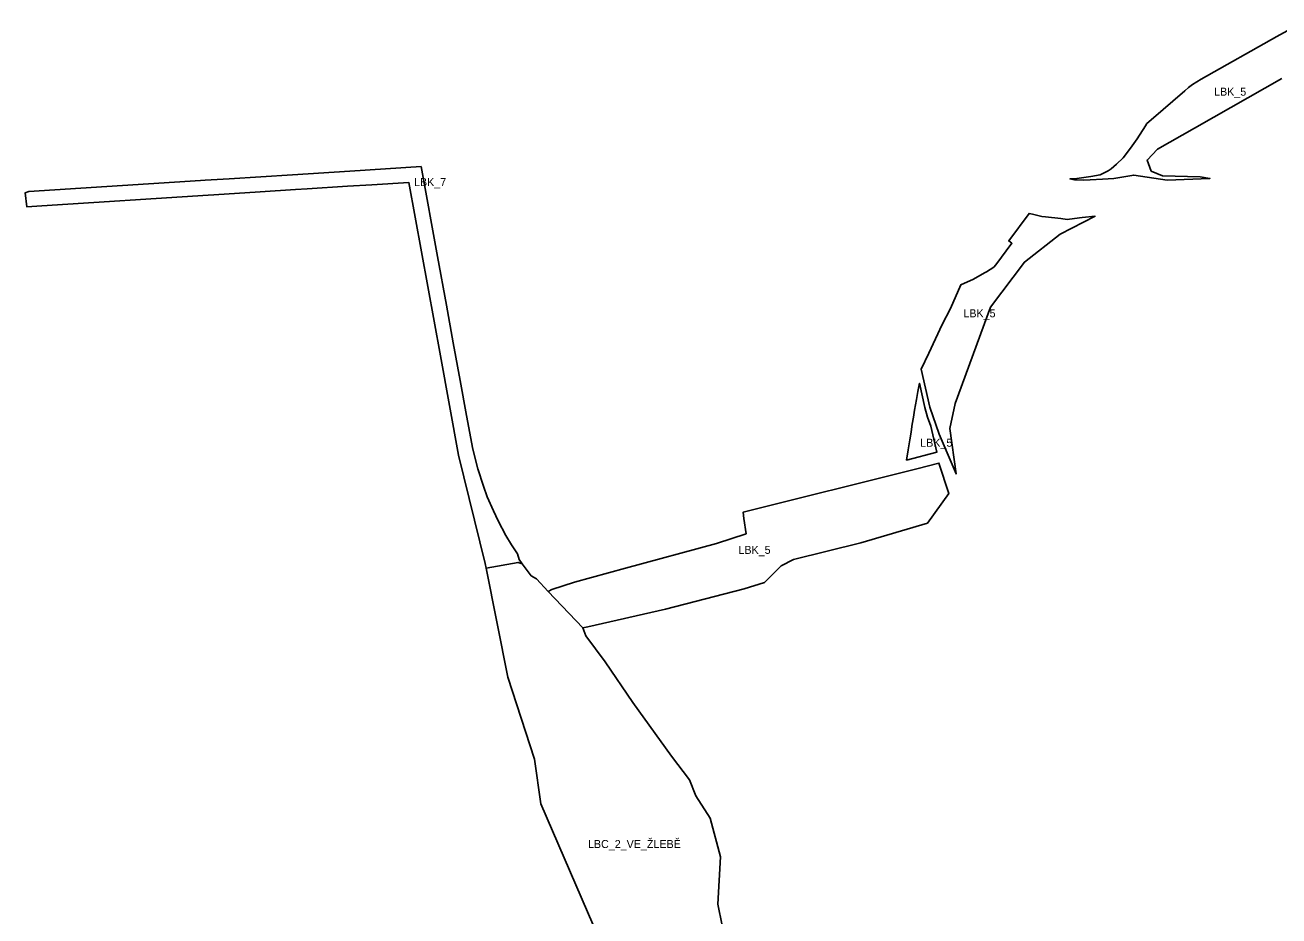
# Model space of a CAD drawing. Extents: x -521939 to -516426, y -1197857 to -1189576.
# Drawn here: x -519963 to -518710, y -1193727 to -1192836 of the extents above; entities that cross this region are included whole.
import ezdxf

# ---------------------------------------------------------------- set-up
doc = ezdxf.new("R2010")
doc.units = 0
doc.layers.add('91270013', color=7, linetype='Continuous')
doc.layers.add('91280013', color=7, linetype='Continuous')

msp = doc.modelspace()

# ---------------------------------------------------------------- linework, layer by layer
at = {"layer": '91270013'}
for points in [[(-519389.47, -1193750.04), (-519447.84, -1193614.85), (-519453.95, -1193570.4), (-519480.86, -1193488.16), (-519502.33, -1193379.15), (-519470.46, -1193373.47), (-519466.38, -1193375.11), (-519457.37, -1193386.9), (-519452.18, -1193390.07), (-519440.32, -1193402.59), (-519405.79, -1193439.04)], [(-519405.79, -1193439.04), (-519402.88, -1193446.79), (-519383.3, -1193472.91), (-519355.68, -1193513.49), (-519316.99, -1193567.29), (-519298.97, -1193590.8), (-519292.71, -1193607.08), (-519278.45, -1193629.39), (-519268.16, -1193667.94), (-519270.68, -1193715.28), (-519266.62, -1193736.71)]]:
    msp.add_lwpolyline(points, dxfattribs=at)
at = {"layer": '91280013'}
for points in [[(-518858.28, -1192959.18), (-518851.6, -1192949.85), (-518843.32, -1192936.91), (-518841.93, -1192934.75), (-518837.69, -1192931.06), (-518804.08, -1192901.83), (-518800.23, -1192898.65), (-518796.23, -1192895.68), (-518792.08, -1192892.91), (-518787.8, -1192890.35), (-518712.04, -1192847.75), (-518691.51, -1192836.21)], [(-518707.15, -1192889.79), (-518774.96, -1192928.3), (-518794.45, -1192939.2), (-518831.52, -1192960.42), (-518841.74, -1192971.22), (-518837.66, -1192982.24), (-518826.37, -1192986.96), (-518788.86, -1192987.81), (-518779.05, -1192989.61), (-518821.67, -1192991.23), (-518855.17, -1192986.26), (-518866.91, -1192988.22), (-518875.1, -1192989.54), (-518886.48, -1192990.45), (-518898.64, -1192990.98), (-518905.82, -1192991.22), (-518911.52, -1192991.08), (-518914.36, -1192990.89), (-518918.87, -1192990), (-518912.11, -1192989.78), (-518897.98, -1192987.5), (-518888.53, -1192985.94), (-518880.78, -1192981.82), (-518877.56, -1192980.06), (-518872.22, -1192975.24), (-518865.75, -1192969.09), (-518858.28, -1192959.18)], [(-519502.33, -1193379.15), (-519503.38, -1193374.77), (-519529.92, -1193266.42), (-519548.08, -1193166.93), (-519579.74, -1192993.48), (-519616.64, -1192995.84), (-519640.92, -1192997.38), (-519681.4, -1192999.94), (-519693.03, -1193000.71), (-519728.13, -1193002.94), (-519774.46, -1193005.9), (-519780.28, -1193006.26), (-519946.52, -1193016.85), (-519961.59, -1193017.82), (-519963.23, -1193004.02), (-519959.5, -1193002.65), (-519787.9, -1192991.72), (-519783.15, -1192991.42), (-519777.13, -1192991.04), (-519759.2, -1192989.89), (-519727.53, -1192987.89), (-519695.85, -1192985.85), (-519638.79, -1192982.16), (-519567.38, -1192977.66), (-519550.99, -1193067.69), (-519542.14, -1193116.18), (-519535.25, -1193153.85), (-519528.39, -1193191.55), (-519522, -1193226.57), (-519515.74, -1193260.34), (-519510.86, -1193279.84), (-519505.08, -1193297.39), (-519501.24, -1193308), (-519495.18, -1193322.01), (-519490.34, -1193332.09), (-519482.58, -1193346.45), (-519476.92, -1193356.09), (-519471.11, -1193364.85), (-519469.48, -1193370.72), (-519466.38, -1193375.11), (-519470.46, -1193373.47), (-519502.33, -1193379.15)], [(-519015.15, -1193090.46), (-519004.43, -1193084.1), (-519002.31, -1193082.85), (-518994.93, -1193078.21), (-518993.12, -1193076.06), (-518976.91, -1193054.31), (-518980, -1193052), (-518959.64, -1193024.58), (-518956.41, -1193025.34), (-518946.89, -1193027.59), (-518943.36, -1193028), (-518927.91, -1193029.78), (-518921.63, -1193030.5), (-518914.19, -1193029.54), (-518906.5, -1193028.54), (-518893.72, -1193027.32), (-518928.64, -1193045.14), (-518964.46, -1193073.28), (-518998.24, -1193118.29), (-519033.58, -1193214.67), (-519039.05, -1193239.66), (-519032.72, -1193285.1), (-519049.46, -1193245.15), (-519058.78, -1193218.39), (-519067.63, -1193180.4), (-519060.07, -1193164.39), (-519046.53, -1193135.65), (-519038.42, -1193119.66), (-519027.86, -1193095.83), (-519015.15, -1193090.46)], [(-519072.39, -1193210.54), (-519070.86, -1193202.48), (-519069.34, -1193194.44), (-519063.8, -1193218.73), (-519061.2, -1193228.34), (-519057.96, -1193237.27), (-519051.78, -1193263.19), (-519082.09, -1193271.2), (-519080.49, -1193261.05), (-519078.89, -1193250.9), (-519078.88, -1193250.89), (-519078.88, -1193250.88), (-519077.66, -1193243.14), (-519077.23, -1193240.44), (-519076.43, -1193235.38), (-519075.3, -1193228.25), (-519074.18, -1193221.13), (-519073.35, -1193215.87), (-519072.39, -1193210.54)], [(-519405.79, -1193439.04), (-519440.32, -1193402.59), (-519436.58, -1193400.77), (-519414.21, -1193393.4), (-519363, -1193379.33), (-519272.27, -1193354.6), (-519242.56, -1193344.82), (-519244.89, -1193329.7), (-519245.64, -1193323.44), (-519072.06, -1193279.85), (-519049.8, -1193274.26), (-519040.03, -1193304.65), (-519061.29, -1193334.23), (-519127.73, -1193353.98), (-519195.16, -1193370.61), (-519207.67, -1193377.01), (-519216.77, -1193386.17), (-519224.13, -1193393.57), (-519244.63, -1193400.06), (-519323.14, -1193420.3), (-519400.65, -1193437.87), (-519405.79, -1193439.04)]]:
    msp.add_lwpolyline(points, dxfattribs=at)

# ---------------------------------------------------------------- texts
at = {"layer": '91270013'}
msp.add_text('LBC_2_VE_ŽLEBĚ', height=8, dxfattribs=at).set_placement((-519400.6, -1193659.09))
at = {"layer": '91280013'}
for s, rotation, p in [('LBK_5', 360, (-518774.8, -1192906.84)), ('LBK_7', 0, (-519574.46, -1192997.21)), ('LBK_5', 360, (-519025.36, -1193128.43)), ('LBK_5', 0, (-519068.52, -1193257.86)), ('LBK_5', 360, (-519250.2, -1193364.99))]:
    msp.add_text(s, height=8, rotation=rotation, dxfattribs=at).set_placement(p)

doc.saveas('drawing.dxf')
